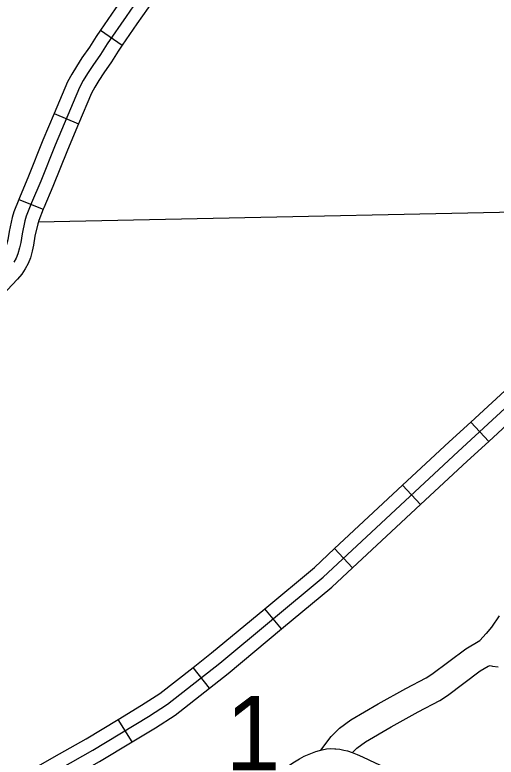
# Model space of a CAD drawing. Extents: x -3711 to 825, y -151 to 1050.
# Drawn here: x -2640.2 to -2609.55, y 230.68 to 277.96 of the extents above; entities that cross this region are included whole.
import ezdxf

# ---------------------------------------------------------------- set-up
doc = ezdxf.new("R2010")
doc.units = 0
for name, color, linetype in [('Level 31', 7, 'Continuous'), ('Level 32', 7, 'Continuous'), ('Level 4', 7, 'Continuous'), ('Level 46', 7, 'Continuous'), ('Level 5', 7, 'Continuous')]:
    doc.layers.add(name, color=color, linetype=linetype)

msp = doc.modelspace()

# ---------------------------------------------------------------- linework, layer by layer
at = {"layer": 'Level 31'}
for points in [[(-2625.455, 228.309), (-2622.493, 230.31), (-2622.082, 230.566), (-2621.777, 230.731), (-2621.458, 230.863), (-2621.031, 231.029), (-2620.798, 231.098), (-2620.624, 231.145), (-2620.355, 231.197), (-2620.088, 231.223), (-2619.821, 231.215)], [(-2619.822, 231.216), (-2619.766, 231.214), (-2619.5, 231.175), (-2619.252, 231.13), (-2619.011, 231.07), (-2618.718, 230.976), (-2618.403, 230.85), (-2618.067, 230.705), (-2617.254, 230.319), (-2616.006, 229.741), (-2614.057, 228.866)]]:
    msp.add_lwpolyline(points, dxfattribs=at)
at = {"layer": 'Level 32'}
for p, q in [((-2634.743, 276.982), (-2633.358, 276.029)), ((-2637.69, 271.68), (-2636.141, 271.025)), ((-2639.956, 266.195), (-2638.395, 265.571)), ((-2610.023, 250.787), (-2611.164, 252.022)), ((-2614.359, 246.764), (-2615.504, 247.995)), ((-2618.693, 242.734), (-2619.838, 243.965)), ((-2623.21, 238.843), (-2624.286, 240.134)), ((-2627.804, 235.074), (-2628.841, 236.397)), ((-2632.74, 231.647), (-2633.613, 233.084))]:
    msp.add_line(p, q, dxfattribs=at)
for points in [[(-2631.682, 281.844), (-2631.797, 281.58), (-2632.001, 281.173), (-2632.163, 280.879), (-2632.538, 280.194), (-2633.11, 279.344), (-2633.806, 278.342), (-2634.743, 276.982)], [(-2630.14, 281.174), (-2630.273, 280.869), (-2630.513, 280.389), (-2630.691, 280.068), (-2631.1, 279.32), (-2631.722, 278.396), (-2632.423, 277.385), (-2633.358, 276.029)], [(-2632.416, 278.87), (-2633.115, 277.864), (-2634.325, 276.106), (-2634.751, 275.441), (-2635.229, 274.742), (-2635.57, 274.23), (-2635.842, 273.769), (-2636.081, 273.326), (-2637.632, 269.658), (-2638.553, 267.355), (-2639.132, 265.99), (-2639.473, 265.137), (-2639.559, 264.847), (-2639.746, 264.011), (-2639.831, 263.465), (-2639.916, 263.124), (-2640.019, 262.732), (-2640.121, 262.459), (-2640.257, 262.203)], [(-2634.743, 276.982), (-2635.025, 276.572), (-2635.453, 275.905), (-2635.926, 275.212), (-2636.282, 274.677), (-2636.574, 274.183), (-2636.84, 273.689), (-2637.69, 271.68)], [(-2633.358, 276.029), (-2633.625, 275.641), (-2634.05, 274.977), (-2634.532, 274.272), (-2634.858, 273.782), (-2635.11, 273.356), (-2635.322, 272.962), (-2636.141, 271.025)], [(-2637.69, 271.68), (-2638.41, 269.978), (-2639.33, 267.675), (-2639.91, 266.311), (-2639.956, 266.195)], [(-2636.141, 271.025), (-2636.855, 269.338), (-2637.776, 267.035), (-2638.355, 265.67), (-2638.395, 265.571)], [(-2639.956, 266.195), (-2640.269, 265.412), (-2640.373, 265.058), (-2640.572, 264.168), (-2640.656, 263.633), (-2640.731, 263.332), (-2640.821, 262.986), (-2640.889, 262.806), (-2640.98, 262.635), (-2641.098, 262.457), (-2641.274, 262.254), (-2642.233, 261.231)], [(-2638.395, 265.571), (-2638.678, 264.862), (-2638.744, 264.637), (-2638.92, 263.854), (-2639.007, 263.298), (-2639.102, 262.916), (-2639.216, 262.478), (-2639.353, 262.112), (-2639.535, 261.771), (-2639.758, 261.437), (-2640.025, 261.128), (-2641.006, 260.082)], [(-2611.164, 252.022), (-2606.815, 256.036)], [(-2675.209, 200.127), (-2672.978, 201.808), (-2670.834, 203.548), (-2668.748, 205.374), (-2663.215, 210.825), (-2661.361, 212.593), (-2659.159, 214.652), (-2655.683, 218.073), (-2654.466, 219.262), (-2653.423, 220.044), (-2652.467, 220.653), (-2645.543, 224.712), (-2640.763, 227.727), (-2638.561, 229.235), (-2637.286, 229.959), (-2635.229, 231.119), (-2631.695, 233.265), (-2630.478, 234.047), (-2627.147, 236.657), (-2620.57, 242.136), (-2611.966, 250.138), (-2605.998, 255.646)], [(-2610.023, 250.787), (-2605.675, 254.801)], [(-2615.504, 247.995), (-2612.537, 250.754), (-2611.164, 252.022)], [(-2614.359, 246.764), (-2611.395, 249.521), (-2610.023, 250.787)], [(-2619.838, 243.965), (-2615.504, 247.995)], [(-2618.693, 242.734), (-2614.359, 246.764)], [(-2624.286, 240.134), (-2621.126, 242.767), (-2619.838, 243.965)], [(-2623.21, 238.843), (-2620.015, 241.505), (-2618.693, 242.734)], [(-2628.841, 236.397), (-2627.675, 237.311), (-2624.286, 240.134)], [(-2627.804, 235.074), (-2626.618, 236.003), (-2623.21, 238.843)], [(-2633.613, 233.084), (-2632.141, 233.977), (-2630.966, 234.733), (-2628.841, 236.397)], [(-2632.74, 231.647), (-2631.249, 232.552), (-2629.991, 233.361), (-2627.804, 235.074)], [(-2638.706, 230.119), (-2637.7, 230.691), (-2635.654, 231.845), (-2633.613, 233.084)], [(-2637.875, 228.658), (-2636.872, 229.228), (-2634.805, 230.394), (-2632.74, 231.647)]]:
    msp.add_lwpolyline(points, dxfattribs=at)
at = {"layer": 'Level 4'}
msp.add_lwpolyline([(-2638.725, 264.775), (-2598.182, 265.63)], dxfattribs=at)
at = {"layer": 'Level 46'}
for points in [[(-2609.352, 239.672), (-2609.842, 238.966), (-2610.18, 238.557), (-2610.587, 238.112)], [(-2620.716, 231.122), (-2620.052, 232.001), (-2619.525, 232.528), (-2618.8, 233.058), (-2617.069, 234.063), (-2615.311, 235.054), (-2614.003, 235.72), (-2613.646, 235.972), (-2611.488, 237.586), (-2610.587, 238.112)], [(-2618.705, 230.971), (-2618.428, 231.248), (-2617.88, 231.649), (-2616.234, 232.604), (-2614.516, 233.572), (-2613.132, 234.277), (-2612.658, 234.612), (-2610.558, 236.182), (-2610.065, 236.47), (-2609.984, 236.502), (-2609.926, 236.509), (-2609.772, 236.47), (-2609.425, 236.436)]]:
    msp.add_lwpolyline(points, dxfattribs=at)

# ---------------------------------------------------------------- texts
at = {"layer": 'Level 5'}
msp.add_text('1', height=4.734, dxfattribs=at).set_placement((-2626.8, 229.835))

doc.saveas('drawing.dxf')
